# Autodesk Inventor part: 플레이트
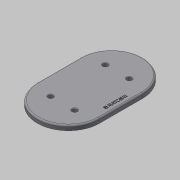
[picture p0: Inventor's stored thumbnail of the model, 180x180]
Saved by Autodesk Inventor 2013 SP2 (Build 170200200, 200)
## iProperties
Created: 2016-08
Part Number: 플레이트
Material: 일반
Document SubType Name: Modeling
Designer: mduedu
Density: 1 g/cm^3
Author: mduedu
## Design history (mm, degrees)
sketch "스케치1" dims "d0" = 220, "d2" = 130
  geometry: L1 (45, 65)-(-45, 65); L2 (-45, 65)-(-45, -65); L3 (-45, -65)-(45, -65); L4 (45, -65)-(45, 65); L5 (45, 65)-(-45, -65); L6 (-45, 65)-(45, -65); 5 further points
  constraints: 12 end point, 5 midpoint, 2 parallel, 2 vertical alignment, 1 coincident, 1 horizontal, 1 perpendicular, 4 other
extrude "돌출1" new body sketch "스케치1" distance "d3" = 10; taper "d4" = 0 deg
sketch "스케치2"
  geometry: L1 (-57, -25)-(57, -25); L2 (57, -25)-(57, 25); L3 (57, 25)-(-57, 25); L4 (-57, 25)-(-57, -25); L5 (-57, -25)-(57, 25); L6 (57, -25)-(-57, 25); C1 r 5 at (-57, 25); C2 r 5 at (57, 25); C3 r 5 at (57, -25); C4 r 5 at (-57, -25); 1 further point
  constraints: 12 end point, 4 centre point, 4 coincident, 3 equal radius, 2 midpoint, 2 parallel, 1 horizontal, 1 perpendicular
  dimensions: "d5" = 114 distance of L2.end L3.end; "d7" = 50 distance of L1.end L2.end; "d8" = 10 diameter of C1
extrude "돌출2" cut sketch "스케치2" stored distance "d9" = 10; taper "d10" = 0 deg
chamfer "모따기1" distance "d11" = 1; stored, may be unused: second distance "d12" = 2, angle "d13" = 45 deg
fillet "모깎기1" dims "d14" = 3
sketch "스케치3"
  geometry: L1 (-45, -65)-(45, -65) reference; 2 further points
  constraints: 1 vertical alignment, 1 other
  dimensions: "d15" = 12 distance from line of point (0, -53) L1
feature "엠보싱1" sketch "스케치3" dims "d16" = 0.5, "d17" = 0
node "솔리드1"
